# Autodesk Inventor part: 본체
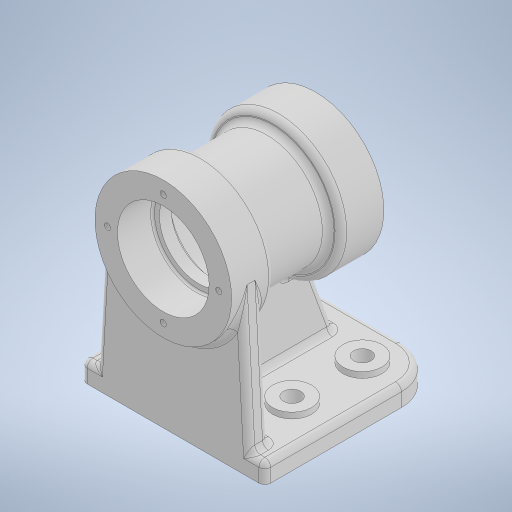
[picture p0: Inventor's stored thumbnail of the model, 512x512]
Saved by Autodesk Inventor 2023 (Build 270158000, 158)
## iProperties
Created: 2024-02
Part Number: 본체
Material: 일반
Document SubType Name: Modeling
Designer: home
Density: 1 g/cm^3
Appearance: 기본값
Author: home
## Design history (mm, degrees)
sketch "스케치1"
  geometry: L1 (-47, -5)-(47, -5); L2 (47, -5)-(47, 5); L3 (47, 5)-(-47, 5); L4 (-47, 5)-(-47, -5); L5 (-47, -5)-(47, 5); L6 (47, -5)-(-47, 5); 1 further point
  constraints: 12 end point, 2 midpoint, 2 parallel, 1 horizontal, 1 perpendicular
  dimensions: "d0" = 94 distance of L2.end L3.end; "d1" = 10 distance of L3.end L1.start
extrude "돌출1" new body sketch "스케치1" distance "d2" = 90; taper "d3" = 0 deg
node "작업 평면1"
sketch "스케치2"
  geometry: L1 (-47, -5)-(47, -5) reference; C1 r 35 at (0, 75); 1 further point
  constraints: 1 centre point, 1 vertical alignment
  dimensions: "d5" = 70 diameter of C1; "d6" = 80 distance from line of L1 C1.centre
extrude "돌출2" join sketch "스케치2" distance "d7" = 22; taper "d8" = 0 deg
sketch "스케치3"
  geometry: C1 r 35 at (0, 0) reference; C2 r 28.5 at (0, 0); 1 further point
  constraints: 1 centre point, 1 coincident
  dimensions: "d9" = 57 diameter of C2
extrude "돌출3" join sketch "스케치3" distance "d10" = 34; taper "d11" = 0 deg
sketch "스케치4"
  geometry: C1 r 28.5 at (0, 0) reference; C2 r 35 at (0, 0); 1 further point
  constraints: 1 centre point, 1 coincident
  dimensions: "d12" = 70 diameter of C2
extrude "돌출4" join sketch "스케치4" distance "d13" = 22; taper "d14" = 0 deg
sketch "스케치5"
  geometry: L1 (-47, 5)-(47, 5) reference; L2 (39, 5)-(34.945, 76.969); L3 (47, -5)-(47, 5) reference; L4 (0, 5)-(39, 5); L5 (34.945, 76.969)-(0, 56.544); L6 (0, 56.544)-(0, 5); 2 further points
  constraints: 8 end point, 1 collinear, 1 midpoint, 1 perpendicular, 1 point on line, 3 other
  dimensions: "d15" = 8 distance from line of L3 L2.start
extrude "돌출5" join sketch "스케치5" distance "d16" = 10; taper "d17" = 0 deg
sketch "스케치6"
  geometry: L1 (5, 0)-(5, -90) reference; L2 (5, -78)-(64.493, -56.346); L3 (64.493, -56.346)-(64.493, 0); L4 (5, 0)-(76.969, 0) reference; L5 (5, -90)-(-5, -90) reference; 2 further points
  constraints: 4 end point, 2 point on line, 1 coincident, 1 vertical
  dimensions: "d18" = 12 distance from line of L5 point (5, -78); "d19" = 70 deg angle of L2 L1
extrude "돌출6" join sketch "스케치6" stored distance "d20" = 10; taper "d21" = 0 deg
sketch "스케치7"
  geometry: L1 (40, -73)-(110, -73) reference; L2 (75, -73)-(75, 5); L3 (110, 5)-(40, 5) reference; L4 (110, 5)-(110, -17) reference; L5 (75, 5)-(98.5, 5); L6 (98.5, 5)-(98.5, -13); L7 (98.5, -13)-(75, -13); L8 (75, -13)-(75, 5); L9 (75, -13)-(95, -13); L10 (95, -13)-(95, -19); L11 (95, -19)-(75, -19); L12 (75, -19)-(75, -13); L13 (75, -19)-(98.5, -19); L14 (98.5, -19)-(98.5, -49); L15 (98.5, -49)-(75, -49); L16 (75, -49)-(75, -19); L17 (75, -49)-(95, -49); L18 (95, -49)-(95, -55); L19 (95, -55)-(75, -55); L20 (75, -55)-(75, -49); L21 (75, -55)-(98.5, -55); L22 (98.5, -55)-(98.5, -73); L23 (98.5, -73)-(75, -73); L24 (75, -73)-(75, -55); 6 further points
  constraints: 42 end point, 10 parallel, 5 horizontal, 5 perpendicular, 3 point on line, 2 midpoint
  dimensions: "d22" = 47 diameter of L6 L2; "d23" = 40 diameter of L10 L2; "d24" = 47 diameter of L14 L2; "d25" = 18 distance of L5.end L6.end; "d26" = 6 distance of L9.end L10.end; "d27" = 30 distance of L13.end L14.end; "d28" = 18 distance of L21.end L22.end
revolve "회전1" sketch "스케치7" stored, may be unused: angle "d29" = 90 deg
fillet "모깎기1" dims "d30" = 3
fillet "모깎기2" dims "d31" = 1
sketch "스케치8" dims "d21" = 0
  geometry: C1 r 35 at (0, 0) reference; A1 r 28.5 centre (0, 0) between (-5, -28.058) and (5, -28.058); A2 r 28.5 centre (0, 0) between (5, -28.058) and (-5, -28.058) reference; 2 further points
  constraints: 1 centre point, 1 coincident, 1 point on circle
  dimensions: "d32" = 57 diameter of A1
hole "구멍1" sketch "스케치8" at (0, 28.5) diameter "d33" = 3.242; stored, may be unused: countersink angle "d37" = 90 deg, drill point angle "d39" = 118 deg; dims "d34" = 8, "d35" = 4, "d36" = 2, "d38" = 10
sketch "스케치9"
  geometry: C1 r 35 at (0, 0) reference; C2 r 28.5 at (0, 0); C3 r 1.621 at (0, 28.5) reference; 2 further points
  constraints: 2 coincident, 1 centre point
  dimensions: "d43" = 57 diameter of C2
hole "구멍2" sketch "스케치9" at (0, 28.5) diameter "d44" = 3.242; stored, may be unused: countersink angle "d48" = 90 deg, drill point angle "d50" = 118 deg; dims "d45" = 8, "d46" = 4, "d47" = 2, "d49" = 10
sketch "스케치10"
  geometry: L1 (8, -90)-(0, -90) reference; L2 (20, -20)-(74, -20); L3 (74, -20)-(74, -56); L4 (74, -56)-(20, -56); L5 (20, -56)-(20, -20); L6 (20, -20)-(74, -56); L7 (74, -20)-(20, -56); L8 (12, -90)-(82, -90) reference; C1 r 10 at (20, -20); C2 r 10 at (74, -20); C3 r 10 at (74, -56); C4 r 10 at (20, -56); 5 further points
  constraints: 12 end point, 4 centre point, 4 coincident, 3 midpoint, 2 parallel, 1 horizontal, 1 perpendicular, 1 vertical alignment
  dimensions: "d54" = 54 distance of L2.start L2.end; "d55" = 36 distance of L4.end L2.start; "d56" = 34 distance between parallel lines of L1 L4; "d57" = 20 diameter of C1; "d58" = 20 diameter of C2; "d59" = 20 diameter of C3; "d60" = 20 diameter of C4
extrude "돌출7" join sketch "스케치10" distance "d61" = 3; taper "d62" = 0 deg
sketch "스케치11"
  geometry: C1 r 10 at (0, 0) reference; C2 r 4.5 at (0, 0); 1 further point
  constraints: 1 centre point, 1 coincident
  dimensions: "d64" = 9 diameter of C2
extrude "돌출8" cut sketch "스케치11" extent not by distance; stored distance "d65" = 0; taper "d66" = 0 deg
sketch "스케치12"
  geometry: C1 r 10 at (0, 0) reference; C2 r 4.5 at (0, 0); 1 further point
  constraints: 1 centre point, 1 coincident
  dimensions: "d67" = 9 diameter of C2
extrude "돌출9" cut sketch "스케치12" extent not by distance; stored distance "d68" = 0; taper "d69" = 0 deg
fillet "모깎기3" dims "d70" = 20
fillet "모깎기4" dims "d71" = 3
fillet "모깎기5" dims "d72" = 3
fillet "모깎기6" dims "d73" = 3
fillet "모깎기7" dims "d74" = 3
fillet "모깎기8" dims "d75" = 3
node "솔리드1"
mirror "미러1"
pattern_circular "원형 패턴1" dims angle "d41" = 360 deg
pattern_circular "원형 패턴2" dims angle "d52" = 360 deg
mirror "미러2"
mirror "미러3"
feature "A9D066F2-1C7D-4E18-AEED-F7BC21143FA4" dims "d44" = 3.242, "d45" = 8, "d46" = 4, "d47" = 2, "d48" = 90 deg, "d49" = 10, "d50" = 118 deg
other parameters: "d4" = 5
